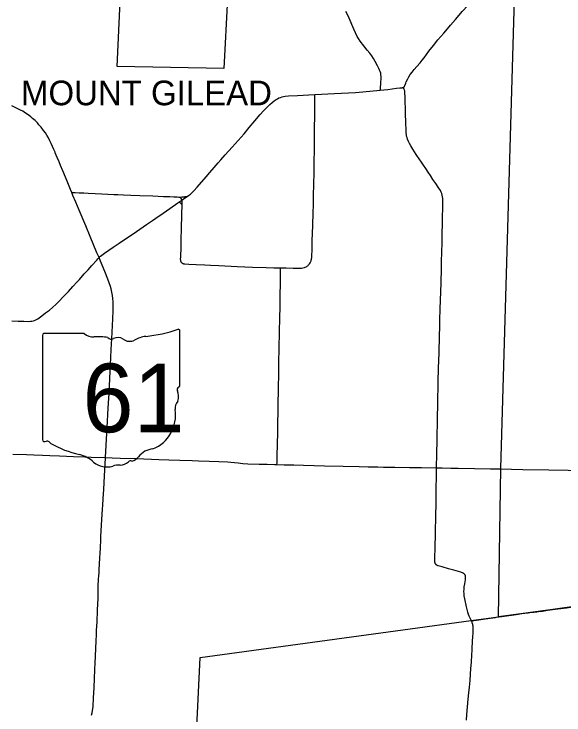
# Model space of a CAD drawing. Extents: x 9078 to 9739, y 4248 to 4966.
# Drawn here: x 9392.4 to 9448.2, y 4556.7 to 4627.8 of the extents above; entities that cross this region are included whole.
import ezdxf

# ---------------------------------------------------------------- set-up
doc = ezdxf.new("R2010")
doc.units = 0
for name, color, linetype in [('GM_X_Corporation', 7, 'Continuous'), ('GM_X_Corporation_Text', 7, 'Continuous'), ('GM_X_County_Road', 7, 'Continuous'), ('GM_X_State_Route', 7, 'Continuous'), ('GM_X_State_Shield', 7, 'Continuous'), ('GM_X_Township', 7, 'Continuous'), ('GM_X_Township_Road', 7, 'Continuous')]:
    doc.layers.add(name, color=color, linetype=linetype)

msp = doc.modelspace()

# ---------------------------------------------------------------- linework, layer by layer
at = {"layer": 'GM_X_Corporation'}
msp.add_lwpolyline([(9414.09, 4629.406), (9413.717, 4622.275), (9402.868, 4622.455), (9403.284, 4631.302)], dxfattribs=at)
at = {"layer": 'GM_X_County_Road'}
for points in [[(9401.699, 4582.811), (9402.376, 4582.793), (9403.195, 4582.76), (9404.833, 4582.699), (9407.127, 4582.619), (9408.11, 4582.59), (9409.257, 4582.557), (9410.485, 4582.503), (9411.141, 4582.482), (9412.206, 4582.45), (9413.189, 4582.412), (9414.089, 4582.368), (9414.415, 4582.341), (9415.147, 4582.256), (9415.637, 4582.205), (9416.129, 4582.172), (9417.277, 4582.14), (9418.096, 4582.125), (9418.833, 4582.102), (9419.094, 4582.094)], [(9419.094, 4582.094), (9419.816, 4582.073), (9420.8, 4582.057), (9421.783, 4582.031), (9422.849, 4582.01), (9423.914, 4581.982), (9425.799, 4581.939), (9427.438, 4581.901), (9428.339, 4581.877), (9429.322, 4581.854), (9429.896, 4581.845), (9431.044, 4581.829), (9432.519, 4581.802), (9433.749, 4581.788), (9435.277, 4581.759)], [(9438.826, 4566.245), (9438.636, 4566.574), (9438.572, 4566.722), (9438.52, 4566.876), (9438.457, 4567.112), (9438.325, 4567.67), (9438.152, 4568.472), (9438.093, 4568.793), (9438.064, 4569.036), (9438.057, 4569.198), (9438.064, 4569.442), (9438.089, 4569.685), (9438.14, 4570.009), (9438.21, 4570.414), (9438.224, 4570.545), (9438.227, 4570.582), (9438.229, 4570.616), (9438.228, 4570.665), (9438.225, 4570.706), (9438.219, 4570.75), (9438.21, 4570.79), (9438.198, 4570.833), (9438.18, 4570.876), (9438.162, 4570.91), (9438.135, 4570.95), (9438.11, 4570.979), (9438.08, 4571.01), (9438.047, 4571.037), (9438.012, 4571.062), (9437.975, 4571.084), (9437.899, 4571.121), (9437.818, 4571.15), (9437.742, 4571.176), (9437.03, 4571.378), (9436.475, 4571.528), (9435.844, 4571.707), (9435.452, 4571.825), (9435.419, 4571.837), (9435.377, 4571.855), (9435.341, 4571.873), (9435.307, 4571.892), (9435.276, 4571.912), (9435.245, 4571.937), (9435.218, 4571.959), (9435.191, 4571.991), (9435.168, 4572.02), (9435.149, 4572.056), (9435.135, 4572.085), (9435.121, 4572.128), (9435.112, 4572.158), (9435.103, 4572.205), (9435.097, 4572.246), (9435.094, 4572.284), (9435.091, 4572.446), (9435.106, 4572.774), (9435.132, 4573.512), (9435.138, 4574.005), (9435.141, 4574.085), (9435.156, 4574.655), (9435.174, 4575.392), (9435.196, 4576.705), (9435.231, 4578.346), (9435.255, 4579.331), (9435.288, 4581.219), (9435.277, 4581.759)], [(9438.309, 4556.18), (9438.355, 4556.752), (9438.482, 4558.304), (9438.542, 4558.957), (9438.606, 4559.526), (9438.676, 4560.178), (9438.729, 4560.832), (9438.771, 4561.404), (9438.813, 4562.058), (9438.848, 4562.787), (9438.886, 4563.275), (9438.898, 4563.437), (9438.935, 4564.165), (9438.965, 4564.654), (9438.984, 4564.98), (9439, 4565.307), (9439, 4565.472), (9438.989, 4565.637), (9438.976, 4565.72), (9438.962, 4565.8), (9438.944, 4565.886), (9438.906, 4566.038), (9438.887, 4566.105), (9438.875, 4566.14), (9438.855, 4566.189), (9438.826, 4566.245)]]:
    msp.add_lwpolyline(points, dxfattribs=at)
at = {"layer": 'GM_X_State_Route'}
for points in [[(9401.701, 4582.837), (9401.905, 4586.475), (9401.947, 4587.211), (9402.015, 4588.358), (9402.066, 4589.259), (9402.133, 4590.816), (9402.24, 4592.946), (9402.281, 4593.765), (9402.334, 4594.83), (9402.443, 4596.877), (9402.476, 4597.697), (9402.483, 4598.19), (9402.471, 4598.602), (9402.447, 4598.93), (9402.407, 4599.257), (9402.352, 4599.582), (9402.28, 4599.903), (9402.213, 4600.141), (9402.081, 4600.531), (9401.936, 4600.915), (9401.622, 4601.674), (9401.19, 4602.737), (9401.044, 4603.081), (9400.837, 4603.568), (9400.146, 4605.235), (9399.701, 4606.293), (9399.039, 4607.884), (9398.68, 4608.703), (9398.401, 4609.393), (9398.279, 4609.69), (9398.15, 4609.999), (9397.805, 4610.83), (9397.363, 4611.889), (9397.141, 4612.418), (9396.989, 4612.799), (9396.803, 4613.254), (9396.611, 4613.699), (9396.58, 4613.77), (9396.517, 4613.909), (9396.454, 4614.049), (9396.196, 4614.643), (9396.059, 4614.942), (9395.908, 4615.234), (9395.741, 4615.518), (9395.605, 4615.724), (9395.416, 4615.991), (9395.166, 4616.315), (9394.956, 4616.566), (9394.79, 4616.749), (9394.557, 4616.981), (9394.313, 4617.202), (9394.123, 4617.36), (9393.861, 4617.559), (9393.59, 4617.747), (9393.311, 4617.921), (9393.095, 4618.041), (9392.728, 4618.225), (9392.205, 4618.464)], [(9400.274, 4556.661), (9400.342, 4556.899), (9400.393, 4557.141), (9400.415, 4557.305), (9400.434, 4557.551), (9400.477, 4558.452), (9400.535, 4559.435), (9400.583, 4560.418), (9400.629, 4561.237), (9400.665, 4562.056), (9400.681, 4562.548), (9400.718, 4563.531), (9400.738, 4564.105), (9400.779, 4564.923), (9400.798, 4565.25), (9400.847, 4566.148), (9400.869, 4566.557), (9400.884, 4566.885), (9400.902, 4567.377), (9400.942, 4568.523), (9400.961, 4569.424), (9400.963, 4569.67), (9400.964, 4569.831), (9400.973, 4569.991), (9400.985, 4570.234), (9401, 4570.478), (9401.025, 4570.802), (9401.044, 4571.128), (9401.065, 4571.535), (9401.088, 4571.942), (9401.104, 4572.186), (9401.12, 4572.431), (9401.132, 4572.675), (9401.156, 4573.082), (9401.187, 4573.653), (9401.199, 4573.898), (9401.212, 4574.224), (9401.225, 4574.469), (9401.242, 4574.795), (9401.311, 4575.941), (9401.341, 4576.508), (9401.404, 4577.556), (9401.428, 4577.962), (9401.467, 4578.613), (9401.529, 4579.595), (9401.598, 4580.906), (9401.698, 4582.79), (9401.699, 4582.811), (9401.701, 4582.837)]]:
    msp.add_lwpolyline(points, dxfattribs=at)
at = {"layer": 'GM_X_State_Shield'}
for p, q in [((9409.241, 4590.11), (9409.241, 4595.638)), ((9395.319, 4595.194), (9395.319, 4584.628)), ((9399.533, 4595.376), (9395.456, 4595.376)), ((9409.239, 4590.112), (9409.241, 4590.11))]:
    msp.add_line(p, q, dxfattribs=at)
for centre, radius, start, end in [((9404.282, 4609.781), 14.764, 275.84447, 288.90645), ((9409.086, 4595.661), 0.155, 351.86209, 97.738), ((9395.479, 4595.216), 0.161, 98.1301, 188.1301), ((9400.504, 4596.602), 1.564, 231.61951, 271.11188), ((9401.023, 4589.444), 5.616, 80.48669, 94.98827), ((9402.298, 4595.271), 0.451, 219.79206, 297.10237), ((9402.96, 4594.05), 0.938, 54.46668, 119.14113), ((9406.165, 4592.148), 2.97, 97.34618, 120.76885), ((9404.171, 4595.725), 1.129, 233.85621, 294.82819), ((9409.205, 4589.704), 0.24, 107.94398, 210.33697), ((9409.075, 4590.089), 0.166, 289.60381, 7.73413), ((9407.679, 4589.006), 1.44, 340.03296, 23.64957), ((9409.796, 4587.797), 1.048, 136.8065, 186.92959), ((9405.109, 4587.094), 3.693, 292.30889, 8.98584), ((9395.48, 4584.604), 0.163, 171.95839, 258.30661), ((9395.505, 4585.686), 1.242, 267.33899, 280.60386), ((9395.759, 4584.018), 0.448, 29.74838, 93.27175), ((9401.412, 4593.511), 10.661, 240.41292, 257.1985), ((9406.666, 4581.661), 2.022, 94.40312, 142.57675), ((9398.233, 4579.881), 3.336, 47.18416, 75.83597), ((9404.103, 4583.604), 1.193, 282.87319, 323.27711), ((9401.841, 4583.966), 2.117, 230.70037, 286.29184), ((9403.219, 4583.174), 1.128, 268.77702, 315.54927), ((9404.239, 4582.151), 0.318, 65.75173, 132.64842), ((9403.064, 4580.312), 1.739, 85.69512, 111.20995)]:
    msp.add_arc(centre, radius, start, end, dxfattribs=at)
at = {"layer": 'GM_X_Township'}
for points in [[(9449.713, 4567.764), (9447.057, 4567.406), (9441.547, 4566.662), (9441.81, 4581.702), (9443.285, 4632.801), (9443.341, 4634.62), (9443.761, 4648.254), (9457.059, 4648.02)], [(9403.572, 4417.317), (9404.179, 4428.722), (9404.315, 4431.281), (9406.691, 4458.18), (9408.516, 4485.114), (9409.016, 4501.409), (9409.03, 4501.874), (9409.589, 4519.144), (9409.927, 4527.297), (9410.369, 4541.158), (9410.412, 4544.235), (9411.301, 4562.535), (9438.791, 4566.274), (9441.547, 4566.662)]]:
    msp.add_lwpolyline(points, dxfattribs=at)
at = {"layer": 'GM_X_Township_Road'}
for points in [[(9436.54, 4626.488), (9436.7, 4626.673), (9437.183, 4627.233), (9437.56, 4627.665), (9437.887, 4628.034), (9438.492, 4628.703), (9438.939, 4629.185), (9439.281, 4629.54), (9439.576, 4629.826), (9439.88, 4630.101), (9440.373, 4630.533), (9440.674, 4630.81), (9441.084, 4631.212), (9441.41, 4631.531)], [(9429.574, 4620.054), (9429.582, 4620.154), (9429.636, 4620.888), (9429.653, 4621.217), (9429.653, 4621.465), (9429.641, 4621.63), (9429.613, 4621.795), (9429.566, 4621.954), (9429.507, 4622.11), (9429.437, 4622.26), (9429.284, 4622.551), (9429.046, 4622.982), (9428.877, 4623.265), (9428.697, 4623.54), (9428.506, 4623.808), (9428.254, 4624.132), (9427.894, 4624.579), (9427.546, 4625.035), (9427.361, 4625.304), (9427.237, 4625.515), (9427.05, 4625.878), (9426.88, 4626.25), (9426.402, 4627.385), (9426.231, 4627.759), (9426.082, 4628.052)], [(9431.932, 4620.361), (9431.961, 4620.379), (9431.991, 4620.406), (9432.013, 4620.432), (9432.034, 4620.466), (9432.067, 4620.538), (9432.147, 4620.771), (9432.211, 4620.924), (9432.356, 4621.221), (9432.479, 4621.436), (9432.615, 4621.642), (9432.813, 4621.905), (9433.02, 4622.161), (9433.288, 4622.472), (9433.613, 4622.841), (9433.82, 4623.094), (9434.017, 4623.355), (9434.506, 4624.015), (9434.958, 4624.599), (9435.421, 4625.175), (9436.003, 4625.865), (9436.54, 4626.488)], [(9422.929, 4619.626), (9424.93, 4619.715), (9427.06, 4619.838), (9427.796, 4619.891), (9429.574, 4620.054)], [(9429.574, 4620.054), (9429.921, 4620.085), (9430.327, 4620.137), (9431.214, 4620.263), (9431.541, 4620.3), (9431.785, 4620.32), (9431.826, 4620.326), (9431.863, 4620.333), (9431.898, 4620.345), (9431.932, 4620.361)], [(9435.277, 4581.759), (9435.308, 4583.178), (9435.33, 4584.573), (9435.371, 4586.787), (9435.398, 4588.263), (9435.451, 4590.476), (9435.487, 4591.87), (9435.527, 4593.428), (9435.567, 4595.15), (9435.597, 4596.051), (9435.625, 4596.789), (9435.655, 4597.855), (9435.712, 4599.658), (9435.738, 4600.478), (9435.75, 4600.969), (9435.763, 4601.543), (9435.778, 4602.198), (9435.789, 4602.69), (9435.836, 4604.576), (9435.858, 4605.56), (9435.872, 4606.462), (9435.888, 4607.282), (9435.9, 4608.02), (9435.915, 4608.511), (9435.924, 4608.922), (9435.916, 4609.087), (9435.895, 4609.252), (9435.861, 4609.414), (9435.814, 4609.573), (9435.754, 4609.727), (9435.682, 4609.876), (9435.452, 4610.22), (9435.189, 4610.615), (9434.916, 4611.024), (9434.65, 4611.424), (9434.432, 4611.75), (9434.179, 4612.128), (9433.968, 4612.445), (9433.819, 4612.669), (9433.679, 4612.868), (9433.589, 4613.003), (9433.221, 4613.54), (9432.863, 4614.087), (9432.653, 4614.437), (9432.538, 4614.653), (9432.431, 4614.873), (9432.337, 4615.098), (9432.286, 4615.252), (9432.246, 4615.409), (9432.218, 4615.569), (9432.199, 4615.73), (9432.18, 4616.056), (9432.168, 4616.712), (9432.144, 4617.777), (9432.095, 4619.335), (9432.074, 4619.827), (9432.054, 4619.99), (9432.036, 4620.072), (9432.007, 4620.152), (9431.932, 4620.361)], [(9409.981, 4609.282), (9410.124, 4609.375), (9410.318, 4609.523), (9410.499, 4609.686), (9410.668, 4609.863), (9410.994, 4610.23), (9411.913, 4611.277), (9412.284, 4611.712), (9412.71, 4612.21), (9413.142, 4612.704), (9413.412, 4613.012), (9413.846, 4613.504), (9414.553, 4614.302), (9415.155, 4614.974), (9415.753, 4615.649), (9416.281, 4616.278), (9416.858, 4616.972), (9417.39, 4617.597), (9417.718, 4617.966), (9418.06, 4618.321), (9418.357, 4618.606), (9418.604, 4618.823), (9418.797, 4618.978), (9419.001, 4619.119), (9419.145, 4619.203), (9419.293, 4619.276), (9419.447, 4619.339), (9419.605, 4619.39), (9419.766, 4619.427), (9419.93, 4619.453), (9420.258, 4619.483), (9421.16, 4619.536), (9422.307, 4619.598), (9422.929, 4619.626)], [(9419.467, 4602.048), (9419.55, 4602.046), (9419.663, 4602.044), (9420.012, 4602.038), (9420.749, 4602.011), (9421.158, 4602), (9421.404, 4602.003), (9421.567, 4602.018), (9421.729, 4602.046), (9421.887, 4602.088), (9421.964, 4602.116), (9422.039, 4602.149), (9422.11, 4602.19), (9422.178, 4602.236), (9422.242, 4602.286), (9422.303, 4602.342), (9422.357, 4602.403), (9422.406, 4602.469), (9422.449, 4602.539), (9422.488, 4602.611), (9422.522, 4602.686), (9422.55, 4602.762), (9422.574, 4602.841), (9422.592, 4602.921), (9422.616, 4603.083), (9422.636, 4603.328), (9422.652, 4603.819), (9422.678, 4604.802), (9422.725, 4606.358), (9422.768, 4607.669), (9422.79, 4608.406), (9422.805, 4609.553), (9422.823, 4610.372), (9422.851, 4611.847), (9422.872, 4612.994), (9422.896, 4613.812), (9422.902, 4614.304), (9422.902, 4615.041), (9422.914, 4616.188), (9422.929, 4617.499), (9422.929, 4618.689), (9422.929, 4619.205), (9422.929, 4619.465), (9422.929, 4619.626)], [(9398.279, 4609.69), (9398.346, 4609.687), (9398.614, 4609.678), (9399.023, 4609.666), (9399.516, 4609.645), (9399.927, 4609.628), (9400.665, 4609.59), (9401.32, 4609.553), (9402.552, 4609.491), (9402.963, 4609.469), (9403.538, 4609.447), (9404.279, 4609.423), (9405.183, 4609.388), (9406.499, 4609.338), (9407.567, 4609.292), (9408.225, 4609.269), (9408.639, 4609.262), (9408.968, 4609.249), (9409.131, 4609.232), (9409.163, 4609.228), (9409.197, 4609.22), (9409.223, 4609.212), (9409.246, 4609.204)], [(9409.246, 4609.204), (9409.272, 4609.22), (9409.286, 4609.225), (9409.305, 4609.227), (9409.444, 4609.233), (9409.622, 4609.241), (9409.709, 4609.253), (9409.796, 4609.272), (9409.891, 4609.296), (9409.906, 4609.298), (9409.915, 4609.299), (9409.923, 4609.299), (9409.93, 4609.298), (9409.936, 4609.297), (9409.948, 4609.294), (9409.96, 4609.291), (9409.981, 4609.282)], [(9409.246, 4609.204), (9409.283, 4609.178), (9409.314, 4609.153), (9409.341, 4609.118), (9409.367, 4609.069), (9409.388, 4609.021), (9409.427, 4608.907)], [(9409.427, 4608.907), (9409.712, 4609.107), (9409.981, 4609.282)], [(9401.044, 4603.081), (9401.078, 4603.124), (9401.134, 4603.187), (9401.202, 4603.245), (9401.329, 4603.344), (9401.598, 4603.534), (9402.483, 4604.129), (9403.096, 4604.541), (9404.859, 4605.742), (9405.875, 4606.435), (9406.479, 4606.859), (9406.814, 4607.096), (9407.561, 4607.603), (9408.237, 4608.067), (9409.042, 4608.635), (9409.145, 4608.708)], [(9409.145, 4608.708), (9409.427, 4608.907)], [(9409.145, 4608.708), (9409.238, 4608.665), (9409.262, 4608.654), (9409.282, 4608.644), (9409.3, 4608.633), (9409.319, 4608.62), (9409.337, 4608.603), (9409.353, 4608.585), (9409.371, 4608.56), (9409.428, 4608.485)], [(9409.428, 4608.485), (9409.407, 4607.433), (9409.378, 4606.04), (9409.348, 4604.893), (9409.331, 4604.155), (9409.294, 4603.172), (9409.289, 4602.926), (9409.295, 4602.844), (9409.3, 4602.804), (9409.31, 4602.763), (9409.322, 4602.721), (9409.338, 4602.687), (9409.354, 4602.654), (9409.38, 4602.617), (9409.406, 4602.589), (9409.436, 4602.558), (9409.474, 4602.531), (9409.504, 4602.513), (9409.537, 4602.496), (9409.579, 4602.481), (9409.616, 4602.47), (9409.659, 4602.463), (9409.699, 4602.457), (9409.741, 4602.453), (9410.15, 4602.433), (9410.887, 4602.401), (9411.788, 4602.358), (9412.361, 4602.331), (9413.18, 4602.294), (9415.063, 4602.199), (9416.618, 4602.13), (9418.011, 4602.069), (9418.764, 4602.057), (9419.322, 4602.048), (9419.39, 4602.048), (9419.467, 4602.048)], [(9409.427, 4608.907), (9409.428, 4608.743), (9409.43, 4608.58), (9409.428, 4608.485)], [(9392.198, 4596.66), (9392.854, 4596.65), (9393.429, 4596.637), (9393.921, 4596.62), (9394.083, 4596.625), (9394.243, 4596.644), (9394.4, 4596.681), (9394.551, 4596.736), (9394.696, 4596.806), (9394.834, 4596.891), (9395.235, 4597.175), (9395.629, 4597.468), (9396.016, 4597.771), (9396.331, 4598.033), (9396.699, 4598.358), (9397.05, 4598.701), (9397.389, 4599.057), (9397.944, 4599.662), (9398.387, 4600.146), (9398.829, 4600.631), (9399.049, 4600.874), (9399.543, 4601.423), (9399.927, 4601.849), (9400.312, 4602.276), (9400.814, 4602.819), (9400.94, 4602.952), (9400.993, 4603.014), (9401.044, 4603.081)], [(9419.094, 4582.094), (9419.097, 4582.269), (9419.1, 4582.423), (9419.111, 4583.087), (9419.139, 4584.07), (9419.171, 4585.462), (9419.189, 4586.445), (9419.202, 4587.346), (9419.219, 4588.247), (9419.248, 4589.64), (9419.273, 4591.524), (9419.291, 4592.589), (9419.317, 4593.735), (9419.355, 4595.702), (9419.382, 4596.849), (9419.411, 4598.241), (9419.428, 4599.388), (9419.45, 4600.371), (9419.461, 4601.518), (9419.465, 4601.853), (9419.466, 4601.947), (9419.467, 4602.008), (9419.467, 4602.048)], [(9392.291, 4583.163), (9393.685, 4583.111), (9394.423, 4583.081), (9395.325, 4583.047), (9396.063, 4583.016), (9397.047, 4582.979), (9398.441, 4582.916), (9399.589, 4582.878), (9400.246, 4582.858), (9401.699, 4582.811)], [(9435.277, 4581.759), (9435.838, 4581.754), (9436.74, 4581.739), (9437.479, 4581.724), (9439.12, 4581.692), (9440.761, 4581.664), (9441.664, 4581.65), (9441.73, 4581.648)], [(9441.73, 4581.648), (9444.043, 4581.608), (9446.669, 4581.566), (9448.638, 4581.528), (9450.279, 4581.494), (9453.807, 4581.419), (9455.448, 4581.389), (9455.618, 4581.385)], [(9441.265, 4566.596), (9441.333, 4566.605), (9441.896, 4566.688), (9442.379, 4566.763), (9442.865, 4566.835), (9443.352, 4566.901), (9443.921, 4566.973), (9444.569, 4567.059), (9444.73, 4567.083), (9445.137, 4567.125), (9445.462, 4567.163), (9445.624, 4567.178), (9446.03, 4567.237), (9446.516, 4567.31), (9447.572, 4567.452), (9448.464, 4567.578), (9449.68, 4567.755), (9450.006, 4567.793), (9450.104, 4567.8)], [(9438.826, 4566.245), (9439.552, 4566.358), (9440.2, 4566.453), (9441.265, 4566.596)]]:
    msp.add_lwpolyline(points, dxfattribs=at)

# ---------------------------------------------------------------- texts
at = {"layer": 'GM_X_Corporation_Text'}
msp.add_text('MOUNT GILEAD', height=2.5, rotation=0.00001, dxfattribs=at).set_placement((9393.132, 4618.537))
at = {"layer": 'GM_X_State_Shield'}
msp.add_text('61', height=6.961, dxfattribs=at).set_placement((9399.37, 4585.373))

doc.saveas('drawing.dxf')
